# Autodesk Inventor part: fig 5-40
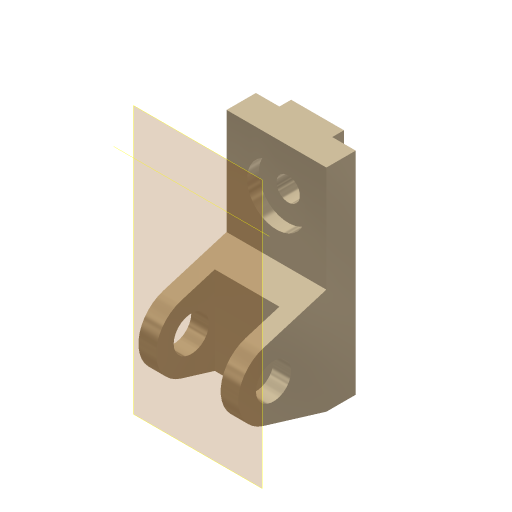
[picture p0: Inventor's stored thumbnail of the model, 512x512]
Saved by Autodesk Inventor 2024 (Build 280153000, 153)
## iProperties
Shininess: 65.0
Angle Display Precision: 2
Document Length Units: 11269
Document Angle Units: 11279
Document Time Units: 11290
Document Mass Units: 11283
Document Length Units Precision: 3
Document Angle Units Precision: 2
Created: 2001-11
Part Number: fig 5-40
Document SubType Name: Modeling
Designer: Renu Muthoo
Density: 1 g/cm^3
Material: Generic
Appearance: Metal-Titanium (Polished)
Density: 0.0
Volumn: 0.0
Area: 0.0
PropertySet Name: Model Information
Control State: 0
Master: False
Checked Out: False
Author: Renu Muthoo
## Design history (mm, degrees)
sketch "Sketch2"
  geometry: L1 (33.257, 104.664)-(33.257, -75.336); L2 (33.257, -75.336)-(8.257, -75.336); L3 (8.257, -75.336)-(-45.451, -59.045); L4 (-45.451, -1.628)-(8.257, 14.664); L5 (8.257, 14.664)-(8.257, 104.664); L6 (8.257, 104.664)-(33.257, 104.664); C1 r 15 at (-36.743, -30.336); A1 r 30 centre (-36.743, -30.336) between (-45.451, -1.628) and (-45.451, -59.045)
  constraints: 12 end point, 2 centre point, 2 equal length, 2 parallel, 2 point on circle, 2 tangent, 1 coincident, 1 perpendicular, 1 vertical
  dimensions: "d0" = 180 distance of L1.start L1.end; "d1" = 30 radius of A1; "d2" = 25 distance of L5.end L1.start; "d3" = 45 distance from line of L2 A1.centre; "d4" = 70 distance from line of L1 A1.centre; "d5" = 30 diameter of C1
extrude "Extrusion1" new body sketch "Sketch2" distance "d6" = 85; taper "d7" = 0 deg
workplane "Work Plane1"
sketch "Sketch3"
  geometry: L1 (15, 62.364)-(70, 62.364); L2 (70, 62.364)-(70, -52.386); L3 (70, -52.386)-(15, -52.386); L4 (15, -52.386)-(15, 62.364); L5 (0, -45)-(0, -28.708) reference
  constraints: 8 end point, 2 parallel, 1 horizontal, 1 perpendicular
  dimensions: "d8" = 55 distance of L1.start L1.end; "d9" = 15 distance between parallel lines of L5 L4
extrude "Extrusion2" cut sketch "Sketch3" distance "d10" = 50; taper "d11" = 0 deg
sketch "Sketch4"
  geometry: L1 (0, 25)-(85, 25) reference; L2 (0, 0)-(0, 25) reference; L3 (20, 25)-(65, 25); L4 (65, 25)-(65, 35); L5 (65, 35)-(20, 35); L6 (20, 35)-(20, 25)
  constraints: 8 end point, 2 parallel, 1 horizontal, 1 perpendicular, 1 point on line
  dimensions: "d12" = 45 distance of L4.end L5.end; "d13" = 10 distance of L3.end L4.end; "d14" = 20 distance between parallel lines of L2 L6
extrude "Extrusion3" join sketch "Sketch4" stored distance "d15" = 50; taper "d16" = 0 deg
sketch "Sketch5"
  geometry: L1 (85, 0)-(85, 90) reference; L2 (0, 90)-(85, 90) reference; 1 further point
  dimensions: "d17" = 42 distance from line of L2 point (42.5, 48); "d18" = 42.5 distance from line of L1 point (42.5, 48)
hole "Hole1" sketch "Sketch5" diameter "d19" = 20; stored, may be unused: countersink angle "d23" = 82 deg, drill point angle "d25" = 118 deg; dims "d20" = 6, "d21" = 50, "d22" = 10, "d24" = 8
workaxis "Work Axis1"
  workplane "Work Plane3"
body "Solid1"
node "Sketch1"
